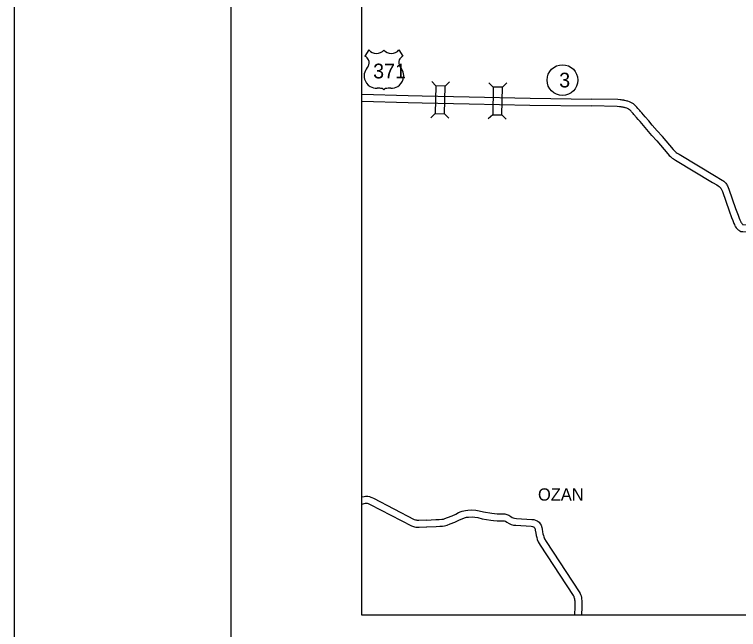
# Model space of a CAD drawing. Extents: x 79818 to 83933, y 50884 to 53307.
# Drawn here: x 80599.5 to 81014.4, y 52602.4 to 52954.9 of the extents above; entities that cross this region are included whole.
import ezdxf

# ---------------------------------------------------------------- set-up
doc = ezdxf.new("R2010")
doc.units = 0
for name, color, linetype in [('Level 15', 7, 'Continuous'), ('Level 20', 7, 'Continuous'), ('Level 22', 7, 'Continuous'), ('Level 27', 7, 'Continuous'), ('Level 6', 7, 'Continuous'), ('R_Border', 7, 'Continuous'), ('R_No Plot', 7, 'Continuous')]:
    doc.layers.add(name, color=color, linetype=linetype)

msp = doc.modelspace()

# ---------------------------------------------------------------- linework, layer by layer
at = {"layer": 'Level 15'}
for points in [[(80798.6, 52909.25), (80825.19, 52908.5), (80833.16, 52908.27)], [(80798.6, 52905.25), (80825.07, 52904.5), (80833.05, 52904.28)], [(80833.15, 52908.27), (80860.11, 52907.65), (80894.96, 52907.04), (80930.27, 52906.49), (80930.28, 52906.49)], [(80970.66, 52885.12), (80967.8, 52888.31), (80964.91, 52891.59), (80962.99, 52893.95), (80961, 52896.28), (80959.87, 52897.49), (80958.93, 52898.57), (80958.49, 52899.05), (80958.24, 52899.38), (80957.85, 52899.84), (80957.4, 52900.3), (80957.12, 52900.64), (80956.74, 52901.11), (80956.23, 52901.74), (80955.83, 52902.23), (80955.43, 52902.64), (80955.23, 52902.83), (80954.79, 52903.25), (80954.23, 52903.67), (80953.84, 52903.91), (80953.48, 52904.11), (80953.05, 52904.35), (80952.72, 52904.49), (80951.87, 52904.86), (80951, 52905.19), (80950.53, 52905.35), (80950.01, 52905.48), (80949.31, 52905.64), (80948.9, 52905.69), (80948.61, 52905.76), (80948.11, 52905.83), (80947.72, 52905.89), (80947.16, 52905.95), (80946.61, 52906.01), (80945.16, 52906.16), (80930.28, 52906.49)], [(80833.06, 52904.27), (80860.02, 52903.65), (80894.89, 52903.04), (80930.19, 52902.49)], [(80967.69, 52882.44), (80964.81, 52885.65), (80961.86, 52889), (80959.91, 52891.39), (80958.01, 52893.61), (80956.89, 52894.82), (80955.96, 52895.89), (80955.42, 52896.47), (80955.11, 52896.88), (80954.89, 52897.15), (80954.43, 52897.62), (80954.02, 52898.11), (80953.62, 52898.6), (80953.12, 52899.23), (80952.85, 52899.56), (80952.65, 52899.77), (80952.47, 52899.93), (80952.19, 52900.2), (80952, 52900.34), (80951.81, 52900.46), (80951.52, 52900.63), (80951.31, 52900.74), (80951.13, 52900.82), (80950.36, 52901.16), (80949.66, 52901.42), (80949.41, 52901.51), (80949.07, 52901.59), (80948.6, 52901.7), (80948.21, 52901.75), (80947.88, 52901.82), (80947.5, 52901.88), (80947.2, 52901.93), (80946.75, 52901.98), (80946.2, 52902.03), (80944.9, 52902.17), (80930.19, 52902.49)], [(80970.66, 52885.12), (80970.7, 52885.08), (80977.02, 52877.63), (80977.68, 52876.81), (80978.06, 52876.44), (80978.34, 52876.2), (80978.71, 52875.88), (80979.27, 52875.52), (80980.38, 52874.84), (81001.55, 52862.15), (81004.16, 52860.6), (81004.94, 52860.03), (81005.45, 52859.73), (81006.04, 52859.34), (81006.55, 52858.82), (81007.12, 52858.28), (81007.47, 52857.7), (81007.8, 52857.3), (81008.03, 52856.69), (81008.51, 52855.85), (81008.9, 52854.78), (81008.91, 52854.75)], [(80967.69, 52882.44), (80973.94, 52875.07), (80974.72, 52874.12), (80975.35, 52873.5), (80975.74, 52873.16), (80976.32, 52872.67), (80977.14, 52872.14), (80978.3, 52871.42), (80999.5, 52858.72), (81001.95, 52857.26), (81002.74, 52856.68), (81003.34, 52856.33), (81003.5, 52856.22), (81003.74, 52855.97), (81003.97, 52855.76), (81004.2, 52855.38), (81004.3, 52855.26), (81004.4, 52854.99), (81004.86, 52854.17), (81005.13, 52853.43)], [(81005.13, 52853.43), (81009.01, 52842.37), (81010.47, 52838.59), (81011.08, 52836.86), (81011.53, 52835.76), (81011.81, 52835.05), (81012.04, 52834.5), (81012.33, 52833.88), (81012.54, 52833.57), (81012.71, 52833.29), (81013.1, 52832.72), (81013.44, 52832.27), (81013.88, 52831.84), (81014.14, 52831.58), (81014.56, 52831.23), (81014.84, 52831.09), (81015.17, 52830.86), (81015.79, 52830.65), (81016.32, 52830.54), (81016.96, 52830.51), (81020.87, 52830.4), (81035.19, 52830.12), (81053.66, 52829.91)], [(81008.91, 52854.75), (81012.76, 52843.76), (81014.23, 52839.98), (81014.82, 52838.28), (81015.25, 52837.25), (81015.53, 52836.54), (81015.7, 52836.1), (81015.81, 52835.87), (81015.89, 52835.75), (81016.07, 52835.46), (81016.35, 52835.05), (81016.44, 52834.94), (81016.69, 52834.69), (81016.76, 52834.62), (81016.91, 52834.52), (81017.13, 52834.5), (81020.96, 52834.39), (81035.25, 52834.12), (81053.7, 52833.91)], [(80798.6, 52678.41), (80799.93, 52678.74), (80800.63, 52678.8), (80801.22, 52678.85), (80802.06, 52678.87), (80802.99, 52678.61), (80803.68, 52678.3), (80804.37, 52678.04), (80805.16, 52677.7), (80828.62, 52665.58), (80829.31, 52665.32), (80829.7, 52665.22), (80830.1, 52665.11), (80830.48, 52665.1), (80831.21, 52665.13), (80835.64, 52665.2)], [(80798.6, 52674.29), (80800.59, 52674.78), (80800.99, 52674.81), (80801.44, 52674.86), (80801.56, 52674.86), (80801.64, 52674.84), (80802.16, 52674.6), (80802.86, 52674.34), (80803.43, 52674.09), (80826.98, 52661.93), (80828.14, 52661.48), (80828.71, 52661.35), (80829.48, 52661.13), (80830.51, 52661.1), (80831.33, 52661.14), (80835.7, 52661.2)], [(80835.58, 52665.19), (80840.99, 52665.44), (80842.89, 52665.56), (80844.44, 52665.68), (80845.29, 52665.75), (80846.18, 52665.98), (80847.72, 52666.67), (80850.23, 52667.66), (80852.37, 52668.62), (80853.92, 52669.41), (80855.54, 52670.03), (80856.14, 52670.24), (80857.92, 52670.73), (80859.36, 52670.8), (80861.66, 52670.97), (80863.85, 52670.87), (80865.85, 52670.5), (80868.35, 52669.88), (80873.02, 52669.06), (80874.51, 52668.85), (80876.2, 52668.73), (80877.12, 52668.71), (80879.06, 52668.7), (80880.53, 52668.64), (80881.68, 52668.42), (80882.85, 52668.01), (80883.89, 52667.22), (80884.79, 52666.66), (80885.33, 52666.42), (80886.01, 52666.27), (80887.12, 52666.15), (80896.05, 52665.56), (80897.14, 52665.41), (80898.16, 52665.1), (80899.03, 52664.75), (80900.09, 52664.05), (80900.76, 52663.05), (80901.23, 52662.26), (80901.74, 52660.98), (80901.9, 52659.87), (80902.12, 52658.36), (80902.32, 52657.2), (80902.6, 52656.35), (80902.87, 52655.46), (80903.29, 52654.49), (80904.16, 52652.88), (80923.15, 52624.05), (80923.65, 52623.1), (80923.88, 52622.44), (80924.17, 52621.7), (80924.38, 52620.7), (80924.48, 52619.84), (80924.53, 52619.03), (80924.58, 52618.01), (80924.6, 52616.77), (80924.53, 52615.43), (80924.45, 52610.7)], [(80835.76, 52661.2), (80841.21, 52661.44), (80843.17, 52661.57), (80844.76, 52661.69), (80845.96, 52661.79), (80847.5, 52662.19), (80849.27, 52662.98), (80851.79, 52663.97), (80854.09, 52665.01), (80855.54, 52665.75), (80856.92, 52666.27), (80857.34, 52666.42), (80858.56, 52666.76), (80859.6, 52666.81), (80861.71, 52666.96), (80863.39, 52666.89), (80865, 52666.59), (80867.53, 52665.96), (80872.4, 52665.11), (80874.09, 52664.87), (80876.02, 52664.73), (80877.07, 52664.71), (80878.97, 52664.7), (80880.08, 52664.65), (80880.65, 52664.55), (80880.92, 52664.45), (80881.62, 52663.92), (80882.92, 52663.12), (80884.07, 52662.59), (80885.37, 52662.32), (80886.77, 52662.17), (80895.65, 52661.58), (80896.28, 52661.49), (80896.83, 52661.32), (80897.17, 52661.19), (80897.21, 52661.16), (80897.37, 52660.92), (80897.64, 52660.47), (80897.85, 52659.95), (80897.94, 52659.3), (80898.17, 52657.72), (80898.43, 52656.23), (80898.78, 52655.16), (80899.1, 52654.09), (80899.69, 52652.73), (80900.73, 52650.82), (80919.7, 52622.02), (80919.98, 52621.49), (80920.13, 52621.05), (80920.32, 52620.56), (80920.43, 52620.06), (80920.49, 52619.48), (80920.54, 52618.8), (80920.58, 52617.88), (80920.6, 52616.85), (80920.53, 52615.57), (80920.45, 52610.7)]]:
    msp.add_lwpolyline(points, dxfattribs=at)
at = {"layer": 'Level 20'}
for p, q in [((80841.01, 52914.01), (80838.58, 52916.56)), ((80846.29, 52913.89), (80848.84, 52916.32)), ((80873.8, 52913.33), (80871.36, 52915.86)), ((80879.08, 52913.23), (80881.61, 52915.68)), ((80840.64, 52898.18), (80838.1, 52895.75)), ((80845.92, 52898.05), (80848.35, 52895.51)), ((80873.53, 52897.49), (80870.99, 52895.05)), ((80878.8, 52897.4), (80881.25, 52894.87))]:
    msp.add_line(p, q, dxfattribs=at)
for points in [[(80845.92, 52898.05), (80846.29, 52913.89), (80841.01, 52914.01), (80840.64, 52898.18)], [(80878.8, 52897.4), (80879.08, 52913.23), (80873.8, 52913.33), (80873.53, 52897.49)]]:
    msp.add_lwpolyline(points, close=True, dxfattribs=at)
at = {"layer": 'Level 22'}
for p, q in [((80802.63, 52934.6), (80800.33, 52931.03)), ((80819.79, 52934.6), (80822.1, 52931.03))]:
    msp.add_line(p, q, dxfattribs=at)
for centre, radius, start, end in [((80806.93, 52938.22), 5.62, 220.075, 319.6701), ((80815.5, 52938.22), 5.62, 220.3299, 319.925), ((80797.31, 52925.85), 6, 30.7809, 59.9883), ((80825.12, 52925.85), 6, 120.0117, 149.2191), ((80798.63, 52927.43), 4.11, 328.8105, 21.2108), ((80823.8, 52927.43), 4.11, 158.7892, 211.1895), ((80806.21, 52919.79), 6.34, 160.9576, 197.3819), ((80809.38, 52919.01), 9.59, 138.9565, 162.6913), ((80813.05, 52919.01), 9.59, 17.3087, 41.0435), ((80816.21, 52919.79), 6.34, 342.6181, 19.0424), ((80807.24, 52919.81), 7.33, 195.1074, 237.1312), ((80815.18, 52919.81), 7.33, 302.8688, 344.8926), ((80807.38, 52922.12), 9.41, 244.0771, 269.5779), ((80815.05, 52922.12), 9.41, 270.4221, 295.9229), ((80807.6, 52895.47), 17.24, 81.1942, 90.9539), ((80809.76, 52910.93), 1.65, 28.0342, 72.9864), ((80812.67, 52910.93), 1.65, 107.0136, 151.9658), ((80814.83, 52895.47), 17.24, 89.0461, 98.8058)]:
    msp.add_arc(centre, radius, start, end, dxfattribs=at)
at = {"layer": 'Level 27'}
msp.add_circle((80913.53, 52917.34), 8.8, dxfattribs=at)
at = {"layer": 'R_Border'}
msp.add_line((80723.6, 51213.92), (80723.6, 53268.52), dxfattribs=at)
at = {"layer": 'R_No Plot'}
for points in [[(80599.53, 53307.47), (83932.93, 53307.47), (83932.93, 51174.09), (80599.53, 51174.09)], [(80798.6, 53193.52), (81459.98, 53193.52), (81459.98, 52610.7), (80798.6, 52610.7)], [(80798.6, 53193.52), (81459.98, 53193.52), (81459.98, 52610.7), (80798.6, 52610.7)]]:
    msp.add_lwpolyline(points, close=True, dxfattribs=at)

# ---------------------------------------------------------------- texts
at = {"layer": 'Level 22'}
msp.add_text('371', height=8.448, dxfattribs=at).set_placement((80805.02, 52918.31))
at = {"layer": 'Level 27'}
msp.add_text('3', height=8.45, dxfattribs=at).set_placement((80911.64, 52913.12))
at = {"layer": 'Level 6'}
msp.add_text('OZAN', height=7.04, dxfattribs=at).set_placement((80899.51, 52676.31))

doc.saveas('drawing.dxf')
